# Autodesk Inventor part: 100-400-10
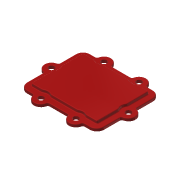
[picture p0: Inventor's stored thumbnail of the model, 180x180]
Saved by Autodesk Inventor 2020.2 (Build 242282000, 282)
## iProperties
Created: 2010-02
Part Number: 100-400-10
Material: Aluminium-6061
Document SubType Name: Modeling
Designer: F.Stasiak
Mass: 1001.87 g
Surface Area: 1002.88 cm^2
Volume: 369.694 cm^3
Density: 2.71 g/cm^3
Appearance: Gładkie — czerwone
Manager: www.cadconsulting.pl
Company: Fabian Stasiak CAD Consulting
Author: F.Stasiak
Subject: Zbiór ćwiczeń. Autodesk Inventor 2020. Kurs podstawowy
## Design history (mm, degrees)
sketch "Szkic1"
  geometry: L1 (90, -75)-(-90, -75); L2 (-95, -70)-(-95, 70); L3 (-90, 75)-(90, 75); L4 (95, 70)-(95, -70); L5 (110, 70)-(110, 24.495); L6 (74.495, 90)-(90, 90); L7 (-25.505, 90)-(25.505, 90); L8 (-90, 90)-(-74.495, 90); L9 (-110, 24.495)-(-110, 70); L10 (-110, -70)-(-110, -24.495); L11 (-74.495, -90)-(-90, -90); L12 (25.505, -90)-(-25.505, -90); L13 (90, -90)-(74.495, -90); L14 (110, -24.495)-(110, -70); C1 r 8 at (110, 0); C2 r 8 at (50, -90); C3 r 8 at (-50, -90); C4 r 8 at (-110, 0); C5 r 8 at (-50, 90); C6 r 8 at (50, 90); A1 r 5 centre (-90, -70) between (-95, -70) and (-90, -75); A2 r 5 centre (-90, 70) between (-90, 75) and (-95, 70); A3 r 5 centre (90, 70) between (95, 70) and (90, 75); A4 r 5 centre (90, -70) between (90, -75) and (95, -70); A5 r 5 centre (115, 24.495) between (110, 24.495) and (114, 19.596); A6 r 20 centre (90, 70) between (110, 70) and (90, 90); A7 r 5 centre (74.495, 95) between (69.596, 94) and (74.495, 90); A8 r 20 centre (50, 90) between (69.596, 94) and (30.404, 94); A9 r 5 centre (25.505, 95) between (25.505, 90) and (30.404, 94); A10 r 5 centre (-25.505, 95) between (-30.404, 94) and (-25.505, 90); A11 r 20 centre (-50, 90) between (-30.404, 94) and (-69.596, 94); A12 r 5 centre (-74.495, 95) between (-74.495, 90) and (-69.596, 94); A13 r 20 centre (-90, 70) between (-90, 90) and (-110, 70); A14 r 5 centre (-115, 24.495) between (-114, 19.596) and (-110, 24.495); A15 r 20 centre (-110, 0) between (-114, 19.596) and (-114, -19.596); A16 r 5 centre (-115, -24.495) between (-110, -24.495) and (-114, -19.596); A17 r 20 centre (-90, -70) between (-110, -70) and (-90, -90); A18 r 5 centre (-74.495, -95) between (-69.596, -94) and (-74.495, -90); A19 r 20 centre (-50, -90) between (-69.596, -94) and (-30.404, -94); A20 r 5 centre (-25.505, -95) between (-25.505, -90) and (-30.404, -94); A21 r 5 centre (25.505, -95) between (30.404, -94) and (25.505, -90); A22 r 20 centre (50, -90) between (30.404, -94) and (69.596, -94); A23 r 5 centre (74.495, -95) between (74.495, -90) and (69.596, -94); A24 r 20 centre (90, -70) between (90, -90) and (110, -70); A25 r 5 centre (115, -24.495) between (114, -19.596) and (110, -24.495); A26 r 20 centre (110, 0) between (114, -19.596) and (114, 19.596); 1 further point
  constraints: 52 point on circle, 32 centre point, 28 end point
  dimensions: "d0" = 16 diameter of C1
extrude "Wyciągnięcie proste1" new body sketch "Szkic1" distance "d1" = 8; taper "d2" = 0 deg
extrude "Wyciągnięcie proste2" join sketch "Szkic1" distance "d3" = 16; taper "d4" = -5 deg
feature "Skorupa1" dims "d7" = 8
sketch "Szkic2"
  geometry: C1 r 8 at (50, 90) reference; C2 r 8 at (-50, 90) reference; C3 r 8 at (-110, 0) reference; C4 r 8 at (-50, -90) reference; C5 r 8 at (50, -90) reference; C6 r 8 at (110, 0) reference; C7 r 20 at (-50, -90); C8 r 20 at (50, 90); A1 r 20 centre (110, 0) between (114, -19.596) and (114, 19.596) reference; A2 r 5 centre (74.495, 95) between (69.596, 94) and (74.495, 90) reference; A3 r 20 centre (50, 90) between (69.596, 94) and (30.404, 94) reference; A4 r 20 centre (-50, 90) between (-30.404, 94) and (-69.596, 94) reference; A5 r 20 centre (-110, 0) between (-114, 19.596) and (-114, -19.596) reference; A6 r 20 centre (-50, -90) between (-69.596, -94) and (-30.404, -94) reference; A7 r 20 centre (50, -90) between (30.404, -94) and (69.596, -94) reference; 5 further points
  constraints: 6 coincident, 2 centre point, 1 concentric, 1 tangent, 12 other
extrude "Wyciągnięcie proste3" cut sketch "Szkic2" extent not by distance; stored distance "d5" = 16; taper "d6" = 0 deg
fillet "Zaokrąglenie2" dims "d9" = 10
fillet "Zaokrąglenie3" dims "d10" = 2
fillet "Zaokrąglenie4" dims "d11" = 5
fillet "Zaokrąglenie5" dims "d12" = 3
node "Bryła1"
other parameters: "d18" = 0, "d19" = 0, "d20" = 0
